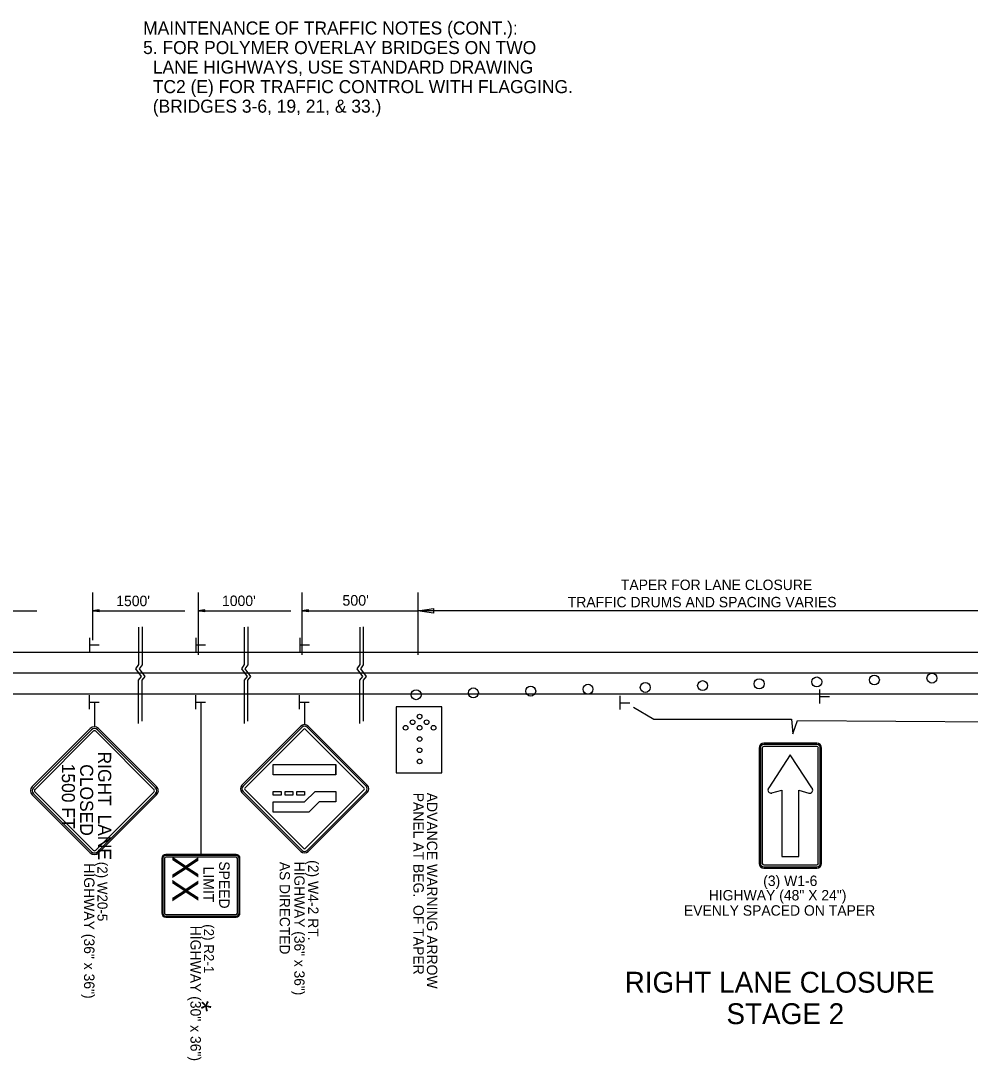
# Model space of a CAD drawing. Extents: x 1930579 to 1937521, y 596183 to 597566.
# Drawn here: x 1935656 to 1936202, y 596928 to 597526 of the extents above; entities that cross this region are included whole.
import ezdxf

# ---------------------------------------------------------------- set-up
doc = ezdxf.new("R2010")
doc.units = 0
for name, color, linetype in [('Default', 7, 'Continuous'), ('P_TC_Signs_Permanent', 7, 'Continuous'), ('P_TC_Signs_Temporary', 7, 'Continuous'), ('R_Annotation', 7, 'Continuous')]:
    doc.layers.add(name, color=color, linetype=linetype)

msp = doc.modelspace()

# ---------------------------------------------------------------- linework, layer by layer
at = {"layer": 'Default'}
for p, q in [((1935696.74, 597197.04), (1935696.74, 597169.66)), ((1935757.62, 597197.04), (1935757.62, 597161.13)), ((1935817.31, 597197.04), (1935817.31, 597161.13)), ((1935884.09, 597197.04), (1935884.09, 597161.13)), ((1935611.55, 597186.51), (1935664.78, 597186.51)), ((1935700.57, 597187.09), (1935696.74, 597186.51)), ((1935696.74, 597186.51), (1935749.97, 597186.51)), ((1935700.57, 597185.94), (1935696.74, 597186.51)), ((1935700.57, 597186.99), (1935697.38, 597186.51)), ((1935700.57, 597186.03), (1935697.38, 597186.51)), ((1935700.57, 597186.89), (1935698.04, 597186.51)), ((1935700.57, 597186.13), (1935698.04, 597186.51)), ((1935700.57, 597186.8), (1935698.67, 597186.51)), ((1935700.57, 597186.23), (1935698.67, 597186.51)), ((1935700.57, 597186.7), (1935699.32, 597186.51)), ((1935700.57, 597186.33), (1935699.32, 597186.51)), ((1935700.57, 597186.6), (1935699.96, 597186.51)), ((1935700.57, 597186.42), (1935699.96, 597186.51)), ((1935700.57, 597185.94), (1935700.57, 597187.09)), ((1935761.45, 597187.09), (1935757.62, 597186.51)), ((1935757.62, 597186.51), (1935810.86, 597186.51)), ((1935761.45, 597185.94), (1935757.62, 597186.51)), ((1935761.45, 597186.99), (1935758.26, 597186.51)), ((1935761.45, 597186.03), (1935758.26, 597186.51)), ((1935761.45, 597186.89), (1935758.92, 597186.51)), ((1935761.45, 597186.13), (1935758.92, 597186.51)), ((1935761.45, 597186.8), (1935759.56, 597186.51)), ((1935761.45, 597186.23), (1935759.56, 597186.51)), ((1935761.45, 597186.7), (1935760.21, 597186.51)), ((1935761.45, 597186.33), (1935760.21, 597186.51)), ((1935761.45, 597186.6), (1935760.85, 597186.51)), ((1935761.45, 597186.42), (1935760.85, 597186.51)), ((1935761.45, 597185.94), (1935761.45, 597187.09)), ((1935821.13, 597187.09), (1935817.31, 597186.51)), ((1935817.31, 597186.51), (1935884.09, 597186.51)), ((1935821.13, 597185.94), (1935817.31, 597186.51)), ((1935821.13, 597186.99), (1935817.95, 597186.51)), ((1935821.13, 597186.03), (1935817.95, 597186.51)), ((1935821.13, 597186.89), (1935818.6, 597186.51)), ((1935821.13, 597186.13), (1935818.6, 597186.51)), ((1935821.13, 597186.8), (1935819.24, 597186.51)), ((1935821.13, 597186.23), (1935819.24, 597186.51)), ((1935821.13, 597186.7), (1935819.89, 597186.51)), ((1935821.13, 597186.33), (1935819.89, 597186.51)), ((1935821.13, 597186.6), (1935820.53, 597186.51)), ((1935821.13, 597186.42), (1935820.53, 597186.51)), ((1935821.13, 597185.94), (1935821.13, 597187.09)), ((1935884.09, 597186.51), (1935892.95, 597187.84)), ((1936251.3, 597186.51), (1935884.09, 597186.51)), ((1935892.95, 597185.18), (1935884.09, 597186.51)), ((1935892.95, 597187.84), (1935892.95, 597185.18)), ((1935695.06, 597170.87), (1935695.06, 597162.89)), ((1935695.18, 597166.9), (1935700.62, 597166.9)), ((1935756.34, 597170.87), (1935756.34, 597162.89)), ((1935756.46, 597166.9), (1935761.9, 597166.9)), ((1935816.02, 597170.87), (1935816.02, 597162.89)), ((1935816.13, 597166.9), (1935821.58, 597166.9)), ((1936503.04, 597162.55), (1935188.53, 597162.55)), ((1936503.04, 597150.55), (1935188.53, 597150.55)), ((1936503.04, 597138.55), (1935188.53, 597138.55)), ((1935695.06, 597129.89), (1935695.06, 597137.87)), ((1935756.31, 597129.89), (1935756.31, 597137.87)), ((1935816, 597129.89), (1935816, 597137.87)), ((1936000.39, 597129.61), (1936000.39, 597137.59)), ((1936115.35, 597133.1), (1936115.35, 597141.08)), ((1936115.47, 597137.07), (1936120.92, 597137.07)), ((1935695.17, 597133.86), (1935700.62, 597133.86)), ((1935756.43, 597133.86), (1935761.87, 597133.86)), ((1935816.11, 597133.86), (1935821.56, 597133.86)), ((1936000.51, 597133.58), (1936005.96, 597133.58))]:
    msp.add_line(p, q, dxfattribs=at)
for points in [[(1935723.24, 597177.07), (1935723.24, 597155.55), (1935721.58, 597153.08), (1935724.81, 597148.65), (1935723.11, 597146.6), (1935723.1, 597121.58)], [(1935725.28, 597177.27), (1935725.28, 597155.46), (1935723.62, 597152.99), (1935726.86, 597148.56), (1935725.15, 597146.52), (1935725.15, 597123.02)], [(1935784.12, 597177.07), (1935784.12, 597155.55), (1935782.46, 597153.08), (1935785.7, 597148.65), (1935783.99, 597146.6), (1935783.99, 597121.58)], [(1935786.17, 597177.27), (1935786.17, 597155.46), (1935784.5, 597152.99), (1935787.74, 597148.56), (1935786.04, 597146.52), (1935786.03, 597123.02)], [(1935850.58, 597177.07), (1935850.58, 597155.55), (1935848.92, 597153.08), (1935852.15, 597148.65), (1935850.45, 597146.6), (1935850.44, 597121.58)], [(1935852.62, 597177.27), (1935852.62, 597155.46), (1935850.96, 597152.99), (1935854.2, 597148.56), (1935852.49, 597146.52), (1935852.49, 597123.02)]]:
    msp.add_lwpolyline(points, dxfattribs=at)
msp.add_lwpolyline([(1935871.59, 597131.26), (1935871.59, 597093.28), (1935897.86, 597093.28), (1935897.86, 597131.26)], close=True, dxfattribs=at)
for centre, radius in [((1936146.77, 597146.64), 2.87), ((1936179.92, 597147.74), 2.87), ((1935948.98, 597140.26), 2.87), ((1935981.96, 597141.31), 2.87), ((1936014.94, 597142.35), 2.87), ((1936047.93, 597143.4), 2.87), ((1936080.46, 597144.43), 2.87), ((1936113.61, 597145.53), 2.87), ((1935883.01, 597138.17), 2.87), ((1935915.99, 597139.22), 2.87), ((1935885.02, 597125.57), 1.34), ((1935876.97, 597119.12), 1.34), ((1935881, 597122.35), 1.34), ((1935885.02, 597119.12), 1.34), ((1935889.05, 597122.35), 1.34), ((1935893.07, 597119.12), 1.34), ((1935885.02, 597112.67), 1.34), ((1935885.02, 597106.22), 1.34), ((1935885.02, 597099.77), 1.34)]:
    msp.add_circle(centre, radius, dxfattribs=at)
at = {"layer": 'P_TC_Signs_Permanent'}
for p, q in [((1935782.77, 597086.11), (1935816.72, 597120.05)), ((1936080.4, 597107.48), (1936080.4, 597041.1)), ((1936081.15, 597107.48), (1936081.15, 597041.1)), ((1936082.27, 597107.48), (1936082.27, 597041.1)), ((1936113.59, 597110.29), (1936083.21, 597110.29)), ((1936113.59, 597109.54), (1936083.21, 597109.54)), ((1936113.59, 597108.41), (1936083.21, 597108.41)), ((1936114.52, 597041.1), (1936114.52, 597107.48)), ((1936115.65, 597041.1), (1936115.65, 597107.48)), ((1936116.4, 597041.1), (1936116.4, 597107.48)), ((1935836.84, 597092.03), (1935836.84, 597098.03)), ((1935816.72, 597047.93), (1935782.77, 597081.87)), ((1935854.9, 597081.87), (1935820.96, 597047.93)), ((1935736.65, 597043.94), (1935736.65, 597012.44)), ((1935737.21, 597043.94), (1935737.21, 597012.44)), ((1935738.15, 597043.94), (1935738.15, 597012.44)), ((1935779.4, 597046.19), (1935738.9, 597046.19)), ((1935779.4, 597045.63), (1935738.9, 597045.63)), ((1935779.4, 597044.69), (1935738.9, 597044.69)), ((1935780.15, 597012.44), (1935780.15, 597043.94)), ((1935781.09, 597012.44), (1935781.09, 597043.94)), ((1935781.65, 597012.44), (1935781.65, 597043.94)), ((1936083.21, 597040.16), (1936113.59, 597040.16)), ((1936083.21, 597039.04), (1936113.59, 597039.04)), ((1936083.21, 597038.29), (1936113.59, 597038.29)), ((1935738.9, 597011.69), (1935779.4, 597011.69)), ((1935738.9, 597010.75), (1935779.4, 597010.75)), ((1935738.9, 597010.19), (1935779.4, 597010.19))]:
    msp.add_line(p, q, dxfattribs=at)
for points in [[(1935817.35, 597119.42), (1935783.41, 597085.47)], [(1935854.26, 597085.47), (1935820.32, 597119.42)], [(1935820.96, 597120.05), (1935837.93, 597103.08), (1935854.9, 597086.11)], [(1935784.47, 597084.41), (1935818.41, 597118.35)], [(1935819.26, 597118.35), (1935853.2, 597084.41)], [(1936110.84, 597084.55), (1936098.4, 597103.54), (1936085.99, 597084.54)], [(1935818.41, 597049.62), (1935784.47, 597083.56)], [(1935853.2, 597083.56), (1935819.26, 597049.62)], [(1936087.76, 597081.59), (1936093.52, 597083.31), (1936093.52, 597045.04), (1936103.27, 597045.04), (1936103.27, 597083.31), (1936109.02, 597081.55)], [(1935783.41, 597082.5), (1935817.35, 597048.56)], [(1935820.32, 597048.56), (1935854.26, 597082.5)]]:
    msp.add_lwpolyline(points, dxfattribs=at)
for points in [[(1935800.84, 597092.03), (1935800.84, 597098.03), (1935836.84, 597098.03), (1935836.84, 597092.03)], [(1935800.84, 597080.39), (1935800.84, 597082.49), (1935805.34, 597082.49), (1935805.34, 597080.39)], [(1935800.84, 597070.49), (1935800.84, 597076.49), (1935818.84, 597076.49), (1935824.84, 597082.49), (1935836.84, 597082.49), (1935836.84, 597076.49), (1935827.32, 597076.49), (1935821.32, 597070.49)], [(1935807.59, 597080.39), (1935807.59, 597082.49), (1935812.09, 597082.49), (1935812.09, 597080.39)], [(1935814.34, 597080.39), (1935814.34, 597082.49), (1935818.84, 597082.49), (1935818.84, 597080.39)]]:
    msp.add_lwpolyline(points, close=True, dxfattribs=at)
for centre, radius, start, end in [((1935818.84, 597117.93), 3, 45, 135), ((1935818.84, 597117.93), 2.1, 45, 135), ((1935818.84, 597117.93), 0.6, 45, 135), ((1936083.21, 597107.48), 2.81, 90, 180), ((1936083.21, 597107.48), 2.06, 90, 180), ((1936083.21, 597107.48), 0.938, 90, 180), ((1936113.59, 597107.48), 2.81, 360, 90), ((1936113.59, 597107.48), 2.06, 360, 90), ((1936113.59, 597107.48), 0.938, 360, 90), ((1935784.9, 597083.99), 3, 135, 225), ((1935784.9, 597083.99), 2.1, 135, 225), ((1935784.9, 597083.99), 0.6, 135, 225), ((1935852.78, 597083.99), 0.6, 315, 45), ((1935852.78, 597083.99), 2.1, 315, 45), ((1935852.78, 597083.99), 3, 315, 45), ((1936087.28, 597083.28), 1.76, 146.59943, 285.96908), ((1936023.19, 597125.54), 75, 326.59943, 326.85697), ((1936109.52, 597083.28), 1.8, 254.03093, 33.47548), ((1936173.58, 597125.64), 75, 213.2286, 213.47548), ((1935818.84, 597050.05), 3, 225, 315), ((1935818.84, 597050.05), 2.1, 225, 315), ((1935818.84, 597050.05), 0.6, 225, 315), ((1935738.9, 597043.94), 2.25, 90, 180), ((1935738.9, 597043.94), 1.69, 90, 180), ((1935738.9, 597043.94), 0.75, 90, 180), ((1935779.4, 597043.94), 2.25, 360, 90), ((1935779.4, 597043.94), 1.69, 360, 90), ((1935779.4, 597043.94), 0.75, 360, 90), ((1936083.21, 597041.1), 2.81, 180, 270), ((1936083.21, 597041.1), 2.06, 180, 270), ((1936083.21, 597041.1), 0.937, 180, 270), ((1936113.59, 597041.1), 2.81, 270, 360), ((1936113.59, 597041.1), 2.06, 270, 360), ((1936113.59, 597041.1), 0.938, 270, 360), ((1935738.9, 597012.44), 2.25, 180, 270), ((1935738.9, 597012.44), 1.69, 180, 270), ((1935738.9, 597012.44), 0.75, 180, 270), ((1935779.4, 597012.44), 2.25, 270, 360), ((1935779.4, 597012.44), 1.69, 270, 360), ((1935779.4, 597012.44), 0.75, 270, 360)]:
    msp.add_arc(centre, radius, start, end, dxfattribs=at)
at = {"layer": 'P_TC_Signs_Temporary'}
for p, q in [((1935662.1, 597085.29), (1935695.51, 597118.71)), ((1935700.28, 597118.71), (1935733.7, 597085.29)), ((1935662.76, 597084.63), (1935696.17, 597118.04)), ((1935663.69, 597083.7), (1935697.1, 597117.11)), ((1935698.69, 597117.11), (1935732.1, 597083.7)), ((1935699.62, 597118.04), (1935733.03, 597084.63)), ((1935695.51, 597047.11), (1935662.1, 597080.52)), ((1935696.17, 597047.77), (1935662.76, 597081.18)), ((1935697.1, 597048.7), (1935663.69, 597082.11)), ((1935732.1, 597082.11), (1935698.69, 597048.7)), ((1935733.03, 597081.18), (1935699.62, 597047.77)), ((1935733.7, 597080.52), (1935700.28, 597047.11))]:
    msp.add_line(p, q, dxfattribs=at)
for centre, radius, start, end in [((1935697.9, 597116.32), 3.37, 45, 135), ((1935697.9, 597116.32), 2.44, 45, 135), ((1935697.9, 597116.32), 1.12, 45, 135), ((1935664.49, 597082.91), 3.37, 135, 225), ((1935664.49, 597082.91), 2.44, 135, 225), ((1935664.49, 597082.91), 1.13, 135, 225), ((1935731.31, 597082.91), 1.13, 315, 45), ((1935731.31, 597082.91), 2.44, 315, 45), ((1935731.31, 597082.91), 3.38, 315, 45), ((1935697.9, 597049.5), 3.38, 225, 315), ((1935697.9, 597049.5), 2.44, 225, 315), ((1935697.9, 597049.5), 1.12, 225, 315)]:
    msp.add_arc(centre, radius, start, end, dxfattribs=at)
at = {"layer": 'R_Annotation'}
for p, q in [((1935697.9, 597133.86), (1935697.9, 597119.69)), ((1935759.15, 597133.86), (1935759.15, 597046.19)), ((1935818.84, 597133.86), (1935818.84, 597120.93))]:
    msp.add_line(p, q, dxfattribs=at)
msp.add_lwpolyline([(1936008.07, 597130.97), (1936019.88, 597124.02), (1936099.08, 597124.02), (1936099.78, 597115.67), (1936102.56, 597123.32), (1936215.81, 597122.63), (1936229.01, 597134.45)], dxfattribs=at)

# ---------------------------------------------------------------- texts
at = {"layer": 'Default'}
for s, height, p in [('TAPER FOR LANE CLOSURE', 5.9999, (1936000.88, 597198.42)), ("1500'", 6, (1935710.46, 597189.15)), ("1000'", 6, (1935771.34, 597189.23)), ("500'", 6.12, (1935840.6, 597189.42)), ('TRAFFIC DRUMS AND SPACING VARIES', 5.9999, (1935970.31, 597188.49)), ('RIGHT LANE CLOSURE', 12, (1936003.05, 596966.66)), ('STAGE 2', 12, (1936061.63, 596948.54))]:
    msp.add_text(s, height=height, rotation=360, dxfattribs=at).set_placement(p)
at = {"layer": 'P_TC_Signs_Permanent'}
for s, height, p in [('XX', 15, (1935742.65, 597045.49)), ('SPEED', 6, (1935769.65, 597042.26)), ('LIMIT', 6, (1935760.65, 597039.17))]:
    msp.add_text(s, height=height, rotation=270, dxfattribs=at).set_placement(p)
at = {"layer": 'P_TC_Signs_Temporary'}
for s, p in [('RIGHT\u2002LANE', (1935700.02, 597105.43)), ('1500 FT', (1935679.15, 597098.43)), ('CLOSED', (1935689.65, 597098.16))]:
    msp.add_text(s, height=7.5, rotation=270, dxfattribs=at).set_placement(p)
at = {"layer": 'R_Annotation'}
for s, height, rotation, p in [('MAINTENANCE OF TRAFFIC NOTES (CONT.): ', 7.5, 360, (1935725.9, 597518.22)), ('5. FOR POLYMER OVERLAY BRIDGES ON TWO', 7.5, 360, (1935725.9, 597506.97)), ('  LANE HIGHWAYS, USE STANDARD DRAWING', 7.5, 360, (1935725.9, 597495.72)), ('  TC2 (E) FOR TRAFFIC CONTROL WITH FLAGGING.  ', 7.5, 360, (1935725.9, 597484.47)), ('  (BRIDGES 3-6, 19, 21, & 33.)', 7.5, 360, (1935725.9, 597473.22)), ('PANEL AT BEG.  OF TAPER', 6, 270, (1935881.44, 597081.75)), ('ADVANCE WARNING ARROW', 6, 270, (1935889.23, 597081.75)), ('(2) W20-5', 5.76, 270, (1935699.63, 597041.99)), ('AS DIRECTED ', 5.9246, 270, (1935804.48, 597041.94)), ('HIGHWAY (36" x 36")', 5.9246, 270, (1935812.91, 597042.05)), ('(2) W4-2 RT.', 6, 270, (1935820.84, 597042.96)), ('HIGHWAY (36" x 36")', 6, 270, (1935691.9, 597041.12)), ('(3) W1-6', 6, 0.00754, (1936082.78, 597028.05)), ('HIGHWAY (48" X 24")', 6, 0.00754, (1936051.44, 597019.75)), ('EVENLY SPACED ON TAPER', 6, 0.00754, (1936037.15, 597010.96)), ('(2) R2-1', 5.76, 270, (1935760.88, 597006.06)), ('HIGHWAY (30" x 36")', 6, 270, (1935753.15, 597005.19)), ('*', 12, 45, (1935766.03, 596950.54))]:
    msp.add_text(s, height=height, rotation=rotation, dxfattribs=at).set_placement(p)

doc.saveas('drawing.dxf')
